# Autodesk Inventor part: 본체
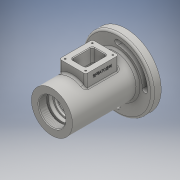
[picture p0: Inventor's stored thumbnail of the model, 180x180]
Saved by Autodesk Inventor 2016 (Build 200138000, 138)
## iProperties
Created: 2017-05
Part Number: 본체
Material: 일반
Document SubType Name: Modeling
Designer: USER
Density: 1 g/cm^3
Appearance: 기본값
Author: USER
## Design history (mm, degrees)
sketch "스케치1"
  geometry: L1 (0, 0)-(119.064, 0); L2 (0, 31)-(99, 31); L3 (99, 31)-(99, 53); L4 (99, 53)-(112, 53); L5 (112, 53)-(112, 31); L6 (112, 31)-(115, 31); L7 (115, 31)-(115, 0); L8 (0, 31)-(0, 0)
  constraints: 16 end point, 4 perpendicular, 3 point on line, 2 horizontal, 1 vertical
  dimensions: "d0" = 62 diameter of L2 L1; "d1" = 106 diameter of L4 L1; "d2" = 115 distance between parallel lines of L7 L8; "d3" = 13 distance of L3.end L4.end; "d4" = 3 distance between parallel lines of L7 L5
revolve "회전1" sketch "스케치1" stored, may be unused: angle "d5" = 90 deg
sketch "스케치2"
  geometry: 2 further points
  constraints: 1 coincident
hole "구멍1" sketch "스케치2" at (0, 0) diameter "d6" = 40.376; stored, may be unused: countersink angle "d10" = 90 deg, drill point angle "d12" = 0 deg; dims "d7" = 12, "d8" = 4, "d9" = 2, "d11" = 12
sketch "스케치3"
  geometry: L1 (-12, -20.188)-(-12, 20.188) reference; L2 (-12, 0)-(-12, 24); L3 (-12, 24)-(-15, 24); L4 (-15, 24)-(-15, 20); L5 (-15, 20)-(-21, 20); L6 (-21, 20)-(-21, 17.5); L7 (-26, 18.5)-(-26, 17.5); L8 (-26, 17.5)-(-37, 17.5); L9 (-37, 17.5)-(-37, 26); L10 (-37, 26)-(-75, 26); L11 (-75, 26)-(-75, 17.5); L12 (-75, 17.5)-(-86, 17.5); L13 (-86, 17.5)-(-86, 16.5); L14 (-115, 31)-(-115, -31) reference; L15 (-12, 0)-(-115, 0); L16 (0, 20.188)-(0, -20.188) reference; L17 (-21, 17.5)-(-24.25, 17.5); L18 (-24.25, 17.5)-(-24.25, 18.5); L19 (-24.25, 18.5)-(-26, 18.5); L20 (-101, 16)-(-115, 22); L21 (-101, 16)-(-101, 12.5); L22 (-93.7, 10)-(-93.7, 12.5); L23 (-93.7, 12.5)-(-101, 12.5); L24 (-93.7, 10)-(-91, 10); L25 (-91, 10)-(-91, 16.5); L26 (-91, 16.5)-(-86, 16.5); L27 (-115, 22)-(-115, 0); 1 further point
  constraints: 48 end point, 12 perpendicular, 4 horizontal, 2 midpoint, 2 point on line, 2 vertical, 1 horizontal alignment
  dimensions: "d13" = 48 diameter of L3 L15; "d14" = 3 distance of L2.end L3.end; "d15" = 40 diameter of L5 L15; "d16" = 21 distance between parallel lines of L6 L16; "d18" = 26 distance between parallel lines of L7 L16; "d19" = 37 diameter of L19 L15; "d20" = 35 diameter of L17 L15; "d21" = 35 diameter of L8 L15; "d22" = 1.75 distance of L18.end L7.start; "d23" = 38 distance of L9.end L10.end; "d24" = 60 distance between parallel lines of L13 L7; "d25" = 44 diameter of L20.end L15; "d26" = 32 diameter of L20.start L15; "d27" = 14 distance between parallel lines of L14 L21; "d29" = 25 diameter of L23 L15; "d30" = 7.3 distance of L22.end L21.end; "d31" = 2.7 distance of L22.start L24.end; "d32" = 20 diameter of L24 L15; "d33" = 33 diameter of L26 L15; "d34" = 52 diameter of L10 L15; "d35" = 11 distance between parallel lines of L9 L7
revolve "회전2" sketch "스케치3" stored, may be unused: angle "d36" = 90 deg
node "작업 평면2"
sketch "스케치5"
  geometry: L1 (-31, -20)-(-81, -20); L2 (-81, -20)-(-81, 20); L3 (-81, 20)-(-31, 20); L4 (-31, 20)-(-31, -20); L5 (-56, -20)-(-56, -24); L6 (0, 31)-(0, -31) reference; 2 further points
  constraints: 10 end point, 2 midpoint, 2 parallel, 1 horizontal, 1 horizontal alignment, 1 perpendicular, 1 vertical
  dimensions: "d41" = 50 distance of L1.start L1.end; "d42" = 40 distance of L1.end L2.end; "d43" = 56 distance between parallel lines of L6 L5
extrude "돌출1" join sketch "스케치5" stored distance "d44" = 10; taper "d45" = 0 deg; dims "d13" = 48, "d14" = 3, "d15" = 40, "d16" = 21, "d18" = 26, "d19" = 37, "d20" = 35, "d21" = 35, "d22" = 1.75, "d23" = 38, "d24" = 60, "d25" = 44, "d26" = 32, "d27" = 14, "d29" = 25, "d30" = 7.3, "d31" = 2.7, "d32" = 20, "d33" = 33, "d34" = 52, "d35" = 11
sketch "스케치6"
  geometry: L1 (-40, -11)-(-72, -11); L2 (-72, -11)-(-72, 11); L3 (-72, 11)-(-40, 11); L4 (-40, 11)-(-40, -11); L5 (-31, -20)-(-81, -20) reference; 4 further points
  constraints: 8 end point, 3 midpoint, 2 parallel, 1 horizontal, 1 horizontal alignment, 1 perpendicular, 1 vertical alignment
  dimensions: "d46" = 32 distance of L1.start L1.end; "d47" = 22 distance of L1.end L2.end
extrude "돌출2" cut sketch "스케치6" distance "d48" = 50; taper "d49" = 0 deg
sketch "스케치7"
  geometry: L1 (-35.5, -15.5)-(-76.5, -15.5); L2 (-76.5, -15.5)-(-76.5, 15.5); L3 (-76.5, 15.5)-(-35.5, 15.5); L4 (-35.5, 15.5)-(-35.5, -15.5); L5 (-31, -20)-(-81, -20) reference; 8 further points
  constraints: 8 end point, 4 coincident, 3 midpoint, 2 parallel, 1 horizontal, 1 horizontal alignment, 1 perpendicular, 1 vertical alignment
  dimensions: "d50" = 41 distance of L1.start L1.end; "d51" = 31 distance of L1.end L2.end
hole "구멍2" sketch "스케치7" at (-35.5, -15.5), (-35.5, 15.5), (-76.5, 15.5), (-76.5, -15.5) diameter "d52" = 2.459; stored, may be unused: countersink angle "d56" = 90 deg, drill point angle "d58" = 118 deg; dims "d53" = 6, "d54" = 4, "d55" = 2, "d57" = 8
sketch "스케치8"
  geometry: C1 r 10 at (0, 0) reference; A1 r 4 centre (0, -41.5) between (0, -45.5) and (0, -37.5); A2 r 4 centre (-41.5, 0) between (-37.5, 0) and (-45.5, 0); A3 r 4 centre (41.5, 0) between (37.5, 0) and (45.5, 0); A4 r 4 centre (0, 41.5) between (0, 45.5) and (0, 37.5); A5 r 45.5 centre (0, 0) between (45.5, 0) and (0, 45.5); A6 r 45.5 centre (0, 0) between (-45.5, 0) and (0, -45.5); A7 r 37.5 centre (0, 0) between (37.5, 0) and (0, 37.5); A8 r 37.5 centre (0, 0) between (-37.5, 0) and (0, -37.5); 1 further point
  constraints: 16 point on circle, 8 centre point, 2 coincident
  dimensions: "d60" = 8 diameter of A1; "d61" = 8 diameter of A2; "d62" = 8 diameter of A3; "d63" = 8 diameter of A4
extrude "돌출3" cut sketch "스케치8" distance "d66" = 20; taper "d67" = 0 deg
fillet "모깎기1" dims "d71" = 3
fillet "모깎기2" dims "d72" = 3
fillet "모깎기3" dims "d73" = 3
fillet "모깎기4" dims "d74" = 3
fillet "모깎기5" dims "d75" = 3
chamfer "모따기2" distance "d76" = 0.7; stored, may be unused: second distance "d77" = 2, angle "d78" = 30 deg
fillet "모깎기6" dims "d79" = 0.3
fillet "모깎기7" dims "d80" = 0.3
chamfer "모따기3" distance "d81" = 1; stored, may be unused: second distance "d82" = 2, angle "d83" = 30 deg
fillet "모깎기8" dims "d84" = 3
chamfer "모따기4" distance "d85" = 1; stored, may be unused: second distance "d86" = 2, angle "d87" = 30 deg
chamfer "모따기5" distance "d88" = 1; stored, may be unused: second distance "d89" = 2, angle "d90" = 30 deg
sketch "스케치10"
  geometry: L1 (78, 75)-(78, 13) reference; L2 (0, 0)-(44, 0) reference; 2 further points
  constraints: 1 other
  dimensions: "d91" = 56 distance from line of point (22, 8) L1; "d92" = 8 distance from line of L2 point (22, 8)
feature "엠보싱1" sketch "스케치10" dims "d0" = 62, "d1" = 106, "d2" = 115, "d3" = 13, "d4" = 3, "d13" = 48, "d14" = 3, "d15" = 40, "d16" = 21, "d18" = 26, "d19" = 37, "d20" = 35, "d21" = 35, "d22" = 1.75, "d23" = 38, "d24" = 60, "d25" = 44, "d26" = 32, "d27" = 14, "d29" = 25, "d30" = 7.3, "d31" = 2.7, "d32" = 20, "d33" = 33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
node "솔리드1"
other parameters: "d40" = 44, "d59" = 83, "d64" = 91, "d65" = 75
